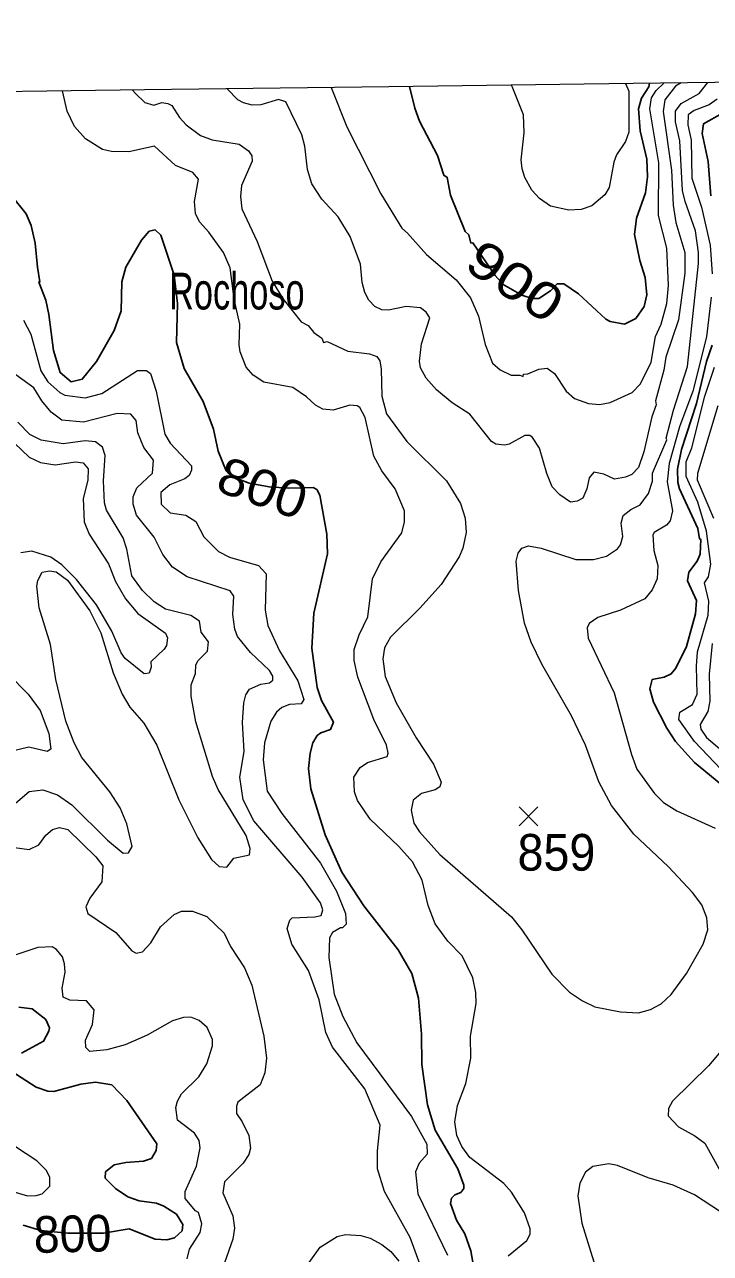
# Model space of a CAD drawing. Extents: x 265 to 291.4, y 7731.5 to 7759.6.
# Drawn here: x 274.292 to 275.788, y 7756.818 to 7759.497 of the extents above; entities that cross this region are included whole.
import ezdxf
from ezdxf.enums import TextEntityAlignment as Align

# ---------------------------------------------------------------- set-up
doc = ezdxf.new("R2010")
doc.units = 0
doc.header["$LTSCALE"] = 0.032
for name, color, linetype, lineweight in [('1', 7, 'Continuous', 25), ('2', 7, 'Continuous', 13), ('21', 7, 'Continuous', 25), ('61', 7, 'Continuous', 13), ('63', 7, 'Continuous', 25)]:
    doc.layers.add(name, color=color, linetype=linetype, lineweight=lineweight)

msp = doc.modelspace()

# ---------------------------------------------------------------- linework, layer by layer
at = {"layer": '1'}
for points in [[(275.655, 7759.3693), (275.6535, 7759.3619), (275.6379, 7759.3367), (275.6307, 7759.3136), (275.6347, 7759.2659), (275.649, 7759.2039), (275.6506, 7759.1657), (275.6466, 7759.1307), (275.6267, 7759.075), (275.622, 7759.04), (275.6339, 7758.9827), (275.6458, 7758.9461), (275.649, 7758.9079), (275.6435, 7758.8825), (275.6252, 7758.8562), (275.6005, 7758.8443), (275.5695, 7758.8499), (275.5599, 7758.8554), (275.5003, 7758.9103), (275.4684, 7758.9318), (275.4533, 7758.9318), (275.439, 7758.9167), (275.4139, 7758.8998), (275.3993, 7758.8998), (275.3767, 7758.9071), (275.3362, 7758.9304), (275.3183, 7758.9503), (275.2698, 7759.0214), (275.2656, 7759.0209), (275.2608, 7759.0392), (275.2529, 7759.0463), (275.221, 7759.1251), (275.2139, 7759.1641), (275.2067, 7759.1689), (275.1924, 7759.2118), (275.1534, 7759.2866), (275.1431, 7759.3152), (275.1318, 7759.3625)], [(275.789, 7759.1243), (275.7827, 7759.1991), (275.7699, 7759.2596), (275.7731, 7759.281), (275.8145, 7759.3041)], [(274.2625, 7759.1251), (274.2951, 7759.0845), (274.3062, 7759.0591), (274.315, 7759.0209), (274.3198, 7758.9684), (274.3253, 7758.9366), (274.3229, 7758.9358), (274.3381, 7758.8968), (274.3452, 7758.865), (274.3548, 7758.787), (274.3699, 7758.7385), (274.3938, 7758.7186), (274.4176, 7758.7242), (274.4486, 7758.7624), (274.4876, 7758.83), (274.5027, 7758.8729), (274.5043, 7758.9366), (274.5131, 7758.9684), (274.5473, 7759.0273), (274.564, 7759.0471), (274.5767, 7759.0495), (274.5895, 7759.0384), (274.6181, 7758.9509), (274.6252, 7758.8889), (274.6236, 7758.8045), (274.6403, 7758.7473), (274.6817, 7758.6757), (274.704, 7758.6152), (274.7143, 7758.5675), (274.7318, 7758.5245), (274.759, 7758.5059), (274.7816, 7758.4973), (274.8254, 7758.4893), (274.8679, 7758.4866), (274.9212, 7758.4879), (274.9291, 7758.4839), (274.9363, 7758.4712), (274.9514, 7758.3861), (274.953, 7758.3432), (274.9227, 7758.2143), (274.9188, 7758.1379), (274.9299, 7758.052), (274.9395, 7758.0234), (274.9657, 7757.9764), (274.9593, 7757.9605), (274.9379, 7757.9533), (274.9299, 7757.947), (274.9204, 7757.9311), (274.9148, 7757.9088), (274.9116, 7757.8754), (274.9164, 7757.8309), (274.9474, 7757.7306), (274.984, 7757.6495), (275.0317, 7757.5755), (275.1065, 7757.48), (275.1367, 7757.4283), (275.1511, 7757.3743), (275.1574, 7757.2963), (275.1582, 7757.2295), (275.1709, 7757.142), (275.1876, 7757.0863), (275.237, 7757.002), (275.2497, 7756.967), (275.2497, 7756.9598), (275.2433, 7756.951), (275.2306, 7756.9455), (275.2234, 7756.9383), (275.2211, 7756.9264), (275.2338, 7756.8906), (275.2521, 7756.8604), (275.2656, 7756.8238), (275.2847, 7756.7124)], [(275.8105, 7757.8412), (275.7533, 7757.8881), (275.7119, 7757.9343), (275.6928, 7757.9629), (275.6641, 7758.0202), (275.6554, 7758.0488), (275.661, 7758.0695), (275.6872, 7758.0743), (275.7023, 7758.0814), (275.7127, 7758.0942), (275.7357, 7758.1411), (275.7556, 7758.2127), (275.7572, 7758.2413), (275.7381, 7758.2843), (275.7405, 7758.3034), (275.7588, 7758.3272), (275.7652, 7758.3424), (275.7668, 7758.3749), (275.7644, 7758.3757), (275.7604, 7758.3988), (275.7206, 7758.4848), (275.7166, 7758.4991), (275.7159, 7758.5277), (275.7246, 7758.5707), (275.7572, 7758.6709), (275.7791, 7758.7624), (275.7917, 7758.7983)], [(274.2856, 7757.2549), (274.3333, 7757.2804), (274.3452, 7757.3027), (274.346, 7757.3098), (274.3381, 7757.3281), (274.3087, 7757.3512), (274.2792, 7757.3551)], [(274.2888, 7756.8794), (274.3277, 7756.8676), (274.3855, 7756.8623), (274.4639, 7756.8623), (274.5202, 7756.8715), (274.5767, 7756.8492), (274.6022, 7756.8476), (274.6189, 7756.8516), (274.6356, 7756.8675), (274.6372, 7756.8811), (274.6236, 7756.9033), (274.5958, 7756.9208), (274.5799, 7756.9272), (274.5417, 7756.9327), (274.5171, 7756.9415), (274.49, 7756.9598), (274.4677, 7756.9821), (274.4685, 7756.9956), (274.4876, 7757.0107), (274.5131, 7757.0163), (274.5513, 7757.0187), (274.5688, 7757.025), (274.5791, 7757.0425), (274.5807, 7757.0569), (274.5147, 7757.1515), (274.4821, 7757.1857), (274.4463, 7757.1913), (274.4144, 7757.1873), (274.3556, 7757.1706), (274.3429, 7757.1714), (274.3174, 7757.1801), (274.2617, 7757.2159)]]:
    msp.add_lwpolyline(points, dxfattribs=at)
at = {"layer": '2'}
for points in [[(275.1081, 7757.7052), (275.0461, 7757.7648), (275.0182, 7757.8054), (275.0119, 7757.8245), (275.0103, 7757.8563), (275.0238, 7757.8778), (275.0397, 7757.8881), (275.0827, 7757.9017), (275.085, 7757.9088), (275.0811, 7757.9263), (275.054, 7757.982), (275.019, 7758.0743), (275.0111, 7758.1109), (275.0111, 7758.1347), (275.0214, 7758.1666), (275.0405, 7758.2063), (275.0508, 7758.2891), (275.0691, 7758.3257), (275.1145, 7758.3893), (275.1208, 7758.4132), (275.1208, 7758.437), (275.1002, 7758.4848), (275.0715, 7758.5245), (275.054, 7758.5563), (275.0349, 7758.6407), (275.023, 7758.6621), (275.0174, 7758.6661), (275.0015, 7758.6677), (274.9649, 7758.6566), (274.9427, 7758.659), (274.9267, 7758.6677), (274.9069, 7758.686), (274.8774, 7758.7059), (274.8138, 7758.7178), (274.7907, 7758.7329), (274.7756, 7758.7504), (274.7621, 7758.7839), (274.7597, 7758.799), (274.7613, 7758.8443), (274.7493, 7758.8984), (274.7406, 7758.9668), (274.7255, 7759.0002), (274.6937, 7759.0448), (274.6738, 7759.067), (274.665, 7759.0853), (274.6626, 7759.1116), (274.6714, 7759.1601), (274.6586, 7759.1752), (274.6213, 7759.1903), (274.5751, 7759.2325), (274.5195, 7759.2198), (274.4813, 7759.2206), (274.4622, 7759.2253), (274.4248, 7759.2484), (274.4009, 7759.2755), (274.385, 7759.3089), (274.3749, 7759.3526)], [(274.5273, 7759.3546), (274.5337, 7759.347), (274.5545, 7759.3272), (274.5736, 7759.3216), (274.5911, 7759.3272), (274.6045, 7759.3256), (274.6133, 7759.3208), (274.63, 7759.2946), (274.6443, 7759.2786), (274.6754, 7759.2556), (274.7008, 7759.246), (274.7597, 7759.2365), (274.7804, 7759.2221), (274.7875, 7759.211), (274.7883, 7759.1999), (274.7653, 7759.1466), (274.7629, 7759.1227), (274.7661, 7759.0957), (274.7995, 7759.0241), (274.8321, 7758.9382), (274.8559, 7758.8984), (274.8949, 7758.8491), (274.9108, 7758.8411), (274.9228, 7758.826), (274.9403, 7758.8133), (274.9442, 7758.8045), (274.9522, 7758.8061), (274.9968, 7758.7854), (275.0445, 7758.7791), (275.0604, 7758.7735), (275.0667, 7758.764), (275.0699, 7758.7457), (275.0715, 7758.6868), (275.0811, 7758.6486), (275.1256, 7758.5882), (275.2123, 7758.5023), (275.2425, 7758.4529), (275.2529, 7758.4211), (275.2553, 7758.3901), (275.2481, 7758.3559), (275.2402, 7758.3368), (275.2004, 7758.2763), (275.1543, 7758.2246), (275.0898, 7758.1618), (275.0771, 7758.1387), (275.0731, 7758.1141), (275.0787, 7758.0759), (275.1025, 7758.0186), (275.1463, 7757.9422), (275.1837, 7757.885), (275.2004, 7757.8452), (275.198, 7757.8356), (275.1877, 7757.8285), (275.1574, 7757.8205), (275.1399, 7757.8062), (275.1352, 7757.7847), (275.1407, 7757.7561), (275.1534, 7757.737), (275.198, 7757.6877), (275.3539, 7757.5516), (275.3762, 7757.5238), (275.4422, 7757.4268), (275.4804, 7757.3878), (275.509, 7757.3687), (275.5361, 7757.3559), (275.5918, 7757.3448), (275.6307, 7757.3424), (275.657, 7757.3496), (275.6801, 7757.3623), (275.7023, 7757.3822), (275.7357, 7757.4283), (275.7723, 7757.492), (275.7819, 7757.5238), (275.7803, 7757.5493), (275.7692, 7757.5779), (275.7485, 7757.6049), (275.6968, 7757.6606), (275.6212, 7757.7322), (275.5719, 7757.7943), (275.5448, 7757.846), (275.5154, 7757.9263), (275.4852, 7757.99), (275.4199, 7758.1029), (275.3969, 7758.1506), (275.3826, 7758.192), (275.369, 7758.2636), (275.3643, 7758.3272), (275.3682, 7758.3447), (275.3762, 7758.3559), (275.3913, 7758.3606), (275.4184, 7758.3559), (275.4947, 7758.3312), (275.5329, 7758.3312), (275.5615, 7758.3384), (275.5854, 7758.3543)], [(275.7242, 7759.3702), (275.7119, 7759.363), (275.6888, 7759.3335), (275.6848, 7759.3081), (275.7031, 7759.18), (275.7063, 7759.1036), (275.7127, 7759.0655), (275.7318, 7759.0002), (275.7318, 7758.9557), (275.7182, 7758.8539), (275.6904, 7758.7719), (275.6864, 7758.7441), (275.6681, 7758.6773), (275.6697, 7758.6685), (275.6602, 7758.6423), (275.6427, 7758.5659), (275.6307, 7758.5317), (275.6164, 7758.5166), (275.6029, 7758.5102), (275.579, 7758.5062), (275.5552, 7758.5174), (275.5337, 7758.5213), (275.5234, 7758.5094), (275.5186, 7758.4848), (275.5098, 7758.4649), (275.4971, 7758.4585), (275.4828, 7758.4561), (275.4597, 7758.472), (275.443, 7758.4895), (275.4311, 7758.5182), (275.4152, 7758.5738), (275.4001, 7758.5969), (275.3937, 7758.6017), (275.3834, 7758.6017), (275.3491, 7758.5826), (275.3388, 7758.5802), (275.3197, 7758.5826), (275.3102, 7758.5881), (275.2632, 7758.6478), (275.2243, 7758.6725), (275.1901, 7758.7011), (275.1678, 7758.7266), (275.1558, 7758.7489), (275.1534, 7758.7632), (275.1574, 7758.8014), (275.1757, 7758.8578), (275.1678, 7758.8706), (275.1558, 7758.8801), (275.124, 7758.8825), (275.0858, 7758.8745), (275.0715, 7758.8753), (275.0556, 7758.8825), (275.0429, 7758.8968), (275.0341, 7758.9135), (275.0286, 7758.935), (275.0246, 7758.9748), (275.0023, 7759.0352), (274.9761, 7759.0782), (274.9403, 7759.1164), (274.9188, 7759.1498), (274.9092, 7759.1816), (274.9029, 7759.2325), (274.8965, 7759.2572), (274.8615, 7759.3288), (274.8456, 7759.3343), (274.8074, 7759.3224), (274.7883, 7759.3216), (274.7692, 7759.3264), (274.7573, 7759.3335), (274.7335, 7759.3573)], [(274.9608, 7759.3603), (274.9952, 7759.2747), (275.0692, 7759.1286), (275.1145, 7759.0535), (275.1272, 7759.0424), (275.1686, 7758.9959), (275.2335, 7758.9409), (275.2648, 7758.9016), (275.2823, 7758.8618), (275.2966, 7758.7998), (275.3125, 7758.7592), (275.3292, 7758.7449), (275.3531, 7758.7329), (275.3722, 7758.7329), (275.3794, 7758.7297), (275.3801, 7758.7353), (275.3897, 7758.7361), (275.4136, 7758.7457), (275.4319, 7758.7481), (275.4478, 7758.7369), (275.4732, 7758.6979), (275.4915, 7758.682), (275.5218, 7758.6709), (275.5456, 7758.6693), (275.5695, 7758.6733), (275.6172, 7758.6955), (275.6355, 7758.7139), (275.6586, 7758.7616), (275.6681, 7758.8173), (275.6801, 7758.8443), (275.6928, 7758.8889), (275.6968, 7758.9286), (275.6928, 7759.0098), (275.6745, 7759.0814), (275.6753, 7759.1959), (275.6554, 7759.3136), (275.6594, 7759.3375), (275.6697, 7759.3534), (275.6864, 7759.3697)], [(275.6025, 7759.3686), (275.6099, 7759.3519), (275.6101, 7759.2627), (275.6029, 7759.2428), (275.583, 7759.2134), (275.5774, 7759.1975), (275.5671, 7759.1418), (275.5576, 7759.1259), (275.5289, 7759.102), (275.5059, 7759.0941), (275.4788, 7759.0925), (275.439, 7759.1012), (275.4152, 7759.1179), (275.3985, 7759.1362), (275.3833, 7759.1641), (275.377, 7759.1832), (275.3754, 7759.2023), (275.3818, 7759.2611), (275.3802, 7759.3009), (275.3555, 7759.3622), (275.3538, 7759.3654)], [(275.6347, 7758.4505), (275.653, 7758.4752), (275.6618, 7758.5015), (275.6618, 7758.519), (275.6926, 7758.5919), (275.6912, 7758.5953), (275.7071, 7758.6566), (275.7381, 7758.752), (275.762, 7758.9764), (275.762, 7759.0002), (275.7556, 7759.048), (275.7326, 7759.1116), (275.727, 7759.1355), (275.7214, 7759.2436), (275.7119, 7759.285), (275.7119, 7759.3089), (275.7238, 7759.3256), (275.7636, 7759.347), (275.7819, 7759.3709)], [(275.8025, 7759.3351), (275.7851, 7759.3224), (275.7525, 7759.3097), (275.7397, 7759.3009), (275.7389, 7759.2786), (275.7461, 7759.2452), (275.7477, 7759.1625), (275.7684, 7759.0989), (275.7874, 7759.0161), (275.7914, 7758.9541)], [(275.7898, 7758.9032), (275.7793, 7758.8168), (275.7495, 7758.6982), (275.7206, 7758.62), (275.6976, 7758.5404), (275.6936, 7758.5007), (275.7055, 7758.437), (275.7, 7758.4155), (275.692, 7758.406), (275.665, 7758.3901), (275.6626, 7758.3845), (275.6642, 7758.3503), (275.6729, 7758.3177), (275.6721, 7758.2891), (275.661, 7758.2652), (275.6451, 7758.2453), (275.5918, 7758.2206), (275.5425, 7758.2047), (275.5234, 7758.1912), (275.5194, 7758.1817), (275.521, 7758.1594), (275.5782, 7758.0401), (275.6156, 7757.9056), (275.6276, 7757.8738), (275.6657, 7757.8205), (275.6856, 7757.8014), (275.7143, 7757.7831), (275.7986, 7757.7449)], [(274.2896, 7758.8531), (274.3055, 7758.822), (274.3277, 7758.7425), (274.3428, 7758.7186), (274.3691, 7758.6948), (274.3795, 7758.6892), (274.424, 7758.6836), (274.4606, 7758.6932), (274.5386, 7758.7433), (274.5576, 7758.7433), (274.5664, 7758.7369), (274.5791, 7758.6979), (274.5982, 7758.6041), (274.6093, 7758.585), (274.6563, 7758.5349), (274.6563, 7758.5261), (274.6507, 7758.5142), (274.6412, 7758.507), (274.6086, 7758.4935), (274.5895, 7758.4768), (274.5902, 7758.4513), (274.6093, 7758.433), (274.6436, 7758.4275), (274.6658, 7758.4139), (274.6833, 7758.3805), (274.7152, 7758.3487), (274.739, 7758.336), (274.8019, 7758.3177), (274.8186, 7758.2994), (274.817, 7758.2207), (274.8225, 7758.1872), (274.848, 7758.1316), (274.8878, 7758.0663), (274.9013, 7758.0258), (274.8949, 7758.0162), (274.8695, 7758.0146), (274.8528, 7758.0082), (274.8416, 7757.9979), (274.8289, 7757.9788), (274.8154, 7757.9311), (274.8122, 7757.8945), (274.8209, 7757.8261), (274.8528, 7757.7768), (274.9371, 7757.6686), (274.9721, 7757.6081), (274.992, 7757.5588), (274.9936, 7757.5357), (274.9856, 7757.5278), (274.9808, 7757.5278), (274.9633, 7757.5174), (274.957, 7757.5063), (274.9554, 7757.4633), (274.9673, 7757.383), (274.9864, 7757.3345), (275.0166, 7757.2772), (275.1359, 7757.1165), (275.1694, 7757.0561), (275.1702, 7757.0346), (275.1527, 7757.0147), (275.1447, 7756.9956), (275.1495, 7756.9479), (275.2147, 7756.8142)], [(275.1797, 7756.7251), (275.1328, 7756.8524), (275.0771, 7756.9526), (275.062, 7757.002), (275.062, 7757.0417), (275.0675, 7757.0974), (275.0341, 7757.177), (274.9633, 7757.2677), (274.949, 7757.2995), (274.9347, 7757.3711), (274.9116, 7757.4347), (274.875, 7757.492), (274.8647, 7757.5262), (274.8703, 7757.5445), (274.8758, 7757.5493), (274.9252, 7757.5516), (274.9387, 7757.5548), (274.9427, 7757.5668), (274.9371, 7757.5827), (274.8973, 7757.6384), (274.7923, 7757.7609), (274.7684, 7757.807), (274.7613, 7757.8563), (274.7708, 7757.912), (274.7676, 7757.9756), (274.77, 7758.0186), (274.7748, 7758.0361), (274.7828, 7758.048), (274.8074, 7758.0592), (274.8265, 7758.0623), (274.8337, 7758.0679), (274.8337, 7758.0767), (274.8265, 7758.0886), (274.7851, 7758.1284), (274.7565, 7758.1634), (274.7509, 7758.1793), (274.7462, 7758.2111), (274.7486, 7758.2509), (274.7406, 7758.2628), (274.6467, 7758.293), (274.6149, 7758.3145), (274.5934, 7758.3416), (274.5743, 7758.3797), (274.5362, 7758.4275), (274.529, 7758.4513), (274.529, 7758.4673), (274.5369, 7758.4871), (274.5712, 7758.5189), (274.5735, 7758.5476), (274.5521, 7758.5754), (274.5393, 7758.6073), (274.5354, 7758.6343), (274.5234, 7758.6478), (274.494, 7758.6494), (274.4208, 7758.6303), (274.3731, 7758.6351), (274.35, 7758.6526), (274.3293, 7758.6773), (274.3118, 7758.7051), (274.2729, 7758.7337)], [(275.8256, 7757.8579), (275.7532, 7757.9343), (275.719, 7757.982), (275.7214, 7757.9979), (275.7485, 7758.0146), (275.7588, 7758.0377), (275.7572, 7758.0981), (275.7596, 7758.13), (275.7827, 7758.2095), (275.7843, 7758.2405), (275.7747, 7758.2803), (275.7835, 7758.293), (275.789, 7758.3209), (275.7795, 7758.3925), (275.7604, 7758.4561), (275.7349, 7758.5118), (275.7349, 7758.5436), (275.7477, 7758.5746), (275.7755, 7758.6868), (275.797, 7758.7504)], [(275.8042, 7758.6661), (275.7596, 7758.5182), (275.7588, 7758.5046), (275.7946, 7758.4211)], [(274.5521, 7757.9741), (274.5807, 7757.9263), (274.6284, 7757.807), (274.6698, 7757.7243), (274.7, 7757.6765), (274.7167, 7757.6614), (274.7334, 7757.6598), (274.7486, 7757.6797), (274.7822, 7757.6869), (274.7842, 7757.7008), (274.7756, 7757.729), (274.7143, 7757.8293), (274.7016, 7757.8579), (274.6658, 7757.9772), (274.6555, 7758.0329), (274.6555, 7758.0576), (274.665, 7758.0822), (274.6658, 7758.1013), (274.6706, 7758.1109), (274.6913, 7758.1308), (274.6929, 7758.1514), (274.6769, 7758.1729), (274.6738, 7758.1968), (274.6547, 7758.2087), (274.599, 7758.223), (274.5743, 7758.2389), (274.5489, 7758.2636), (274.5258, 7758.2954), (274.5147, 7758.3535), (274.5067, 7758.3782), (274.4709, 7758.4386), (274.4662, 7758.4545), (274.4638, 7758.5023), (274.4677, 7758.5579), (274.4622, 7758.5762), (274.4463, 7758.5874), (274.424, 7758.5897), (274.3763, 7758.5834), (274.3285, 7758.5913), (274.3031, 7758.6033), (274.2776, 7758.6303)], [(274.2697, 7758.585), (274.3023, 7758.554), (274.327, 7758.5428), (274.3588, 7758.5372), (274.4033, 7758.5436), (274.42, 7758.542), (274.4304, 7758.5285), (274.4296, 7758.5038), (274.42, 7758.4641), (274.4216, 7758.4132), (274.4327, 7758.3861), (274.4749, 7758.3217), (274.49, 7758.2827), (274.5123, 7758.2453), (274.5393, 7758.2135), (274.599, 7758.1705), (274.6038, 7758.1602), (274.6014, 7758.1435), (274.5966, 7758.1355), (274.5672, 7758.1077), (274.568, 7758.0965), (274.564, 7758.083), (274.5529, 7758.0814), (274.5115, 7758.1148), (274.5028, 7758.1276), (274.4821, 7758.1745), (274.4487, 7758.2318), (274.4049, 7758.2875), (274.3731, 7758.3193), (274.3492, 7758.336), (274.3079, 7758.3495), (274.284, 7758.3455)], [(275.5854, 7758.3543), (275.5918, 7758.363), (275.5965, 7758.3813), (275.5934, 7758.41), (275.5973, 7758.4267), (275.614, 7758.4402), (275.6347, 7758.4505)], [(274.2466, 7757.7776), (274.3023, 7757.8253), (274.3317, 7757.8285), (274.3635, 7757.8181), (274.3954, 7757.7958), (274.4725, 7757.7187), (274.5067, 7757.6908), (274.5187, 7757.6916), (274.5266, 7757.7052), (274.5147, 7757.7545), (274.5004, 7757.7895), (274.4781, 7757.8245), (274.4168, 7757.8993), (274.4001, 7757.9311), (274.3818, 7757.9788), (274.3604, 7758.0695), (274.3484, 7758.1459), (274.3238, 7758.2254), (274.319, 7758.2732), (274.3206, 7758.2851), (274.3301, 7758.3034), (274.346, 7758.3066), (274.3612, 7758.3042), (274.3858, 7758.2859)], [(274.3858, 7758.2859), (274.4343, 7758.2191), (274.4582, 7758.1713), (274.4852, 7758.0838), (274.5051, 7758.0377), (274.5218, 7758.0091), (274.5521, 7757.9741)], [(275.7914, 7758.1475), (275.7851, 7758.0806), (275.7867, 7758.0218), (275.7819, 7757.9995), (275.7652, 7757.9709), (275.7668, 7757.9613), (275.7795, 7757.943), (275.8129, 7757.9144)], [(274.2561, 7758.0814), (274.2999, 7758.0377), (274.3261, 7758.0019), (274.3452, 7757.9518), (274.3492, 7757.9176), (274.3413, 7757.912), (274.3015, 7757.9215), (274.2617, 7757.912)], [(274.2538, 7757.7052), (274.3023, 7757.6988), (274.323, 7757.7091), (274.3381, 7757.7298), (274.3532, 7757.7426), (274.3683, 7757.7465), (274.3866, 7757.7426), (274.4471, 7757.6829), (274.463, 7757.663), (274.4606, 7757.628), (274.4343, 7757.5922), (274.4256, 7757.5739), (274.4303, 7757.5588)], [(275.2465, 7757.4665), (275.2155, 7757.4991), (275.1877, 7757.5365), (275.1725, 7757.5763), (275.159, 7757.632), (275.1383, 7757.6718), (275.1081, 7757.7052)], [(274.4303, 7757.5588), (274.4908, 7757.5174), (274.5258, 7757.4777), (274.5354, 7757.4729), (274.5489, 7757.4753), (274.5672, 7757.4952), (274.5887, 7757.5302)], [(274.5887, 7757.5302), (274.6181, 7757.5572), (274.634, 7757.5644), (274.6579, 7757.5644), (274.6897, 7757.5524), (274.7271, 7757.5159), (274.7414, 7757.4872), (274.7716, 7757.4403), (274.7875, 7757.4029), (274.8138, 7757.2915), (274.8193, 7757.2438), (274.8162, 7757.212), (274.8058, 7757.1857), (274.7573, 7757.1475), (274.7541, 7757.1388), (274.7541, 7757.1229), (274.7668, 7757.1046), (274.7812, 7757.0752), (274.7844, 7757.0473), (274.7812, 7757.0338), (274.7684, 7757.0147), (274.7279, 7756.9741), (274.7247, 7756.9503), (274.7462, 7756.9001), (274.7501, 7756.8731), (274.7462, 7756.8492), (274.7096, 7756.7458)], [(274.6547, 7757.3329), (274.6388, 7757.3321), (274.6149, 7757.3249), (274.5592, 7757.2939), (274.5115, 7757.2724), (274.4717, 7757.2621), (274.4343, 7757.2581), (274.4256, 7757.2669), (274.4248, 7757.2828), (274.4399, 7757.317), (274.4439, 7757.3488), (274.4272, 7757.3687), (274.3906, 7757.3703), (274.3763, 7757.3766), (274.3739, 7757.3965), (274.3802, 7757.4315), (274.3794, 7757.449), (274.3747, 7757.4649), (274.3619, 7757.4809), (274.3524, 7757.4864), (274.3206, 7757.4848), (274.2729, 7757.4689)], [(275.3467, 7756.8126), (275.3873, 7756.846), (275.3945, 7756.8596), (275.3945, 7756.8715), (275.3825, 7756.9065), (275.3539, 7756.9511), (275.3372, 7756.9701), (275.2632, 7757.0274), (275.2457, 7757.0513), (275.2346, 7757.0752), (275.2306, 7757.1046), (275.2362, 7757.1404), (275.2545, 7757.1881), (275.2656, 7757.2438), (275.2648, 7757.2915), (275.2768, 7757.3631), (275.276, 7757.387), (275.2696, 7757.4188), (275.2465, 7757.4665)], [(274.6722, 7757.2032), (274.6897, 7757.2311), (274.7016, 7757.2708), (274.7016, 7757.2844), (274.6905, 7757.3106), (274.673, 7757.3257), (274.6547, 7757.3329)], [(275.8193, 7757.2693), (275.7835, 7757.2271), (275.7055, 7757.1499), (275.6968, 7757.134), (275.696, 7757.1181), (275.7182, 7757.0942), (275.7541, 7757.0743), (275.7755, 7757.0584), (275.8097, 7756.9964)], [(274.6467, 7756.8063), (274.6515, 7756.827), (274.6746, 7756.8636), (274.6785, 7756.8826), (274.6714, 7756.9073), (274.665, 7756.9105), (274.642, 7756.9375), (274.642, 7756.9526), (274.6666, 7757.0083), (274.6746, 7757.0481), (274.673, 7757.064), (274.6626, 7757.0799), (274.6252, 7757.1086), (274.6221, 7757.1364), (274.6252, 7757.1499), (274.634, 7757.1658), (274.6722, 7757.2032)], [(274.2665, 7756.9526), (274.2983, 7756.9431), (274.3174, 7756.9439), (274.3301, 7756.9479), (274.3468, 7756.9646), (274.3468, 7756.9845), (274.3389, 7756.9996), (274.319, 7757.0195), (274.2721, 7757.0505)], [(275.8097, 7756.9089), (275.7533, 7756.9455), (275.7063, 7756.9669), (275.6522, 7756.9829), (275.5854, 7757.0099), (275.5663, 7757.0131), (275.5313, 7757.0075), (275.5154, 7756.9948), (275.5027, 7756.9709), (275.4987, 7756.9431), (275.5074, 7756.8842), (275.5337, 7756.7999)], [(274.8408, 7756.6981), (274.9365, 7756.8314), (274.9737, 7756.8548), (274.992, 7756.8588), (275.0254, 7756.8572), (275.0461, 7756.8508), (275.0715, 7756.8373), (275.0906, 7756.8222), (275.1081, 7756.8007)]]:
    msp.add_lwpolyline(points, dxfattribs=at)
at = {"layer": '21'}
for p, q in [((275.3704, 7757.7914), (275.4116, 7757.7502)), ((275.4116, 7757.7914), (275.3704, 7757.7502))]:
    msp.add_line(p, q, dxfattribs=at)
at = {"layer": '63', "lineweight": 13}
msp.add_lwpolyline([(285.7494, 7759.4974), (285.2163, 7759.4908), (284.6831, 7759.4841), (284.15, 7759.4775), (283.6169, 7759.4708), (283.0837, 7759.4641), (282.5506, 7759.4574), (282.0174, 7759.4507), (281.4843, 7759.444), (280.9511, 7759.4372), (280.418, 7759.4305), (279.8848, 7759.4237), (279.3517, 7759.4169), (278.8185, 7759.4101), (278.2854, 7759.4032), (277.7522, 7759.3964), (277.2191, 7759.3895), (276.6859, 7759.3826), (276.1528, 7759.3757), (275.6196, 7759.3688), (275.0864, 7759.3619), (274.5533, 7759.355), (274.0201, 7759.348)], dxfattribs=at)

# ---------------------------------------------------------------- texts
at = {"layer": '61'}
for s, rotation, width, p in [('900', 326.206, 1.25, (275.3397, 7758.9045)), ('800', 340.491, 1.1, (274.7977, 7758.4493)), ('800', 1.244, 0.95, (274.3975, 7756.8207))]:
    msp.add_text(s, height=0.08, rotation=rotation, dxfattribs=dict(at, width=width)).set_placement(p, align=Align.CENTER)
at = {"layer": '61', "width": 0.7}
msp.add_text('Rochoso', height=0.08, dxfattribs=at).set_placement((274.6072, 7758.8762))
at = {"layer": '61', "width": 0.95}
msp.add_text('859', height=0.08, dxfattribs=at).set_placement((275.452, 7757.6525), align=Align.CENTER)

doc.saveas('drawing.dxf')
